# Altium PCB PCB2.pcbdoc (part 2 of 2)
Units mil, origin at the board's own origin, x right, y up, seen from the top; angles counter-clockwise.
Board outline 4275 x 4381.77 mil, 2 copper layers (Top Layer, Bottom Layer); 56 components, 70 nets, 265 pads, 133 vias.
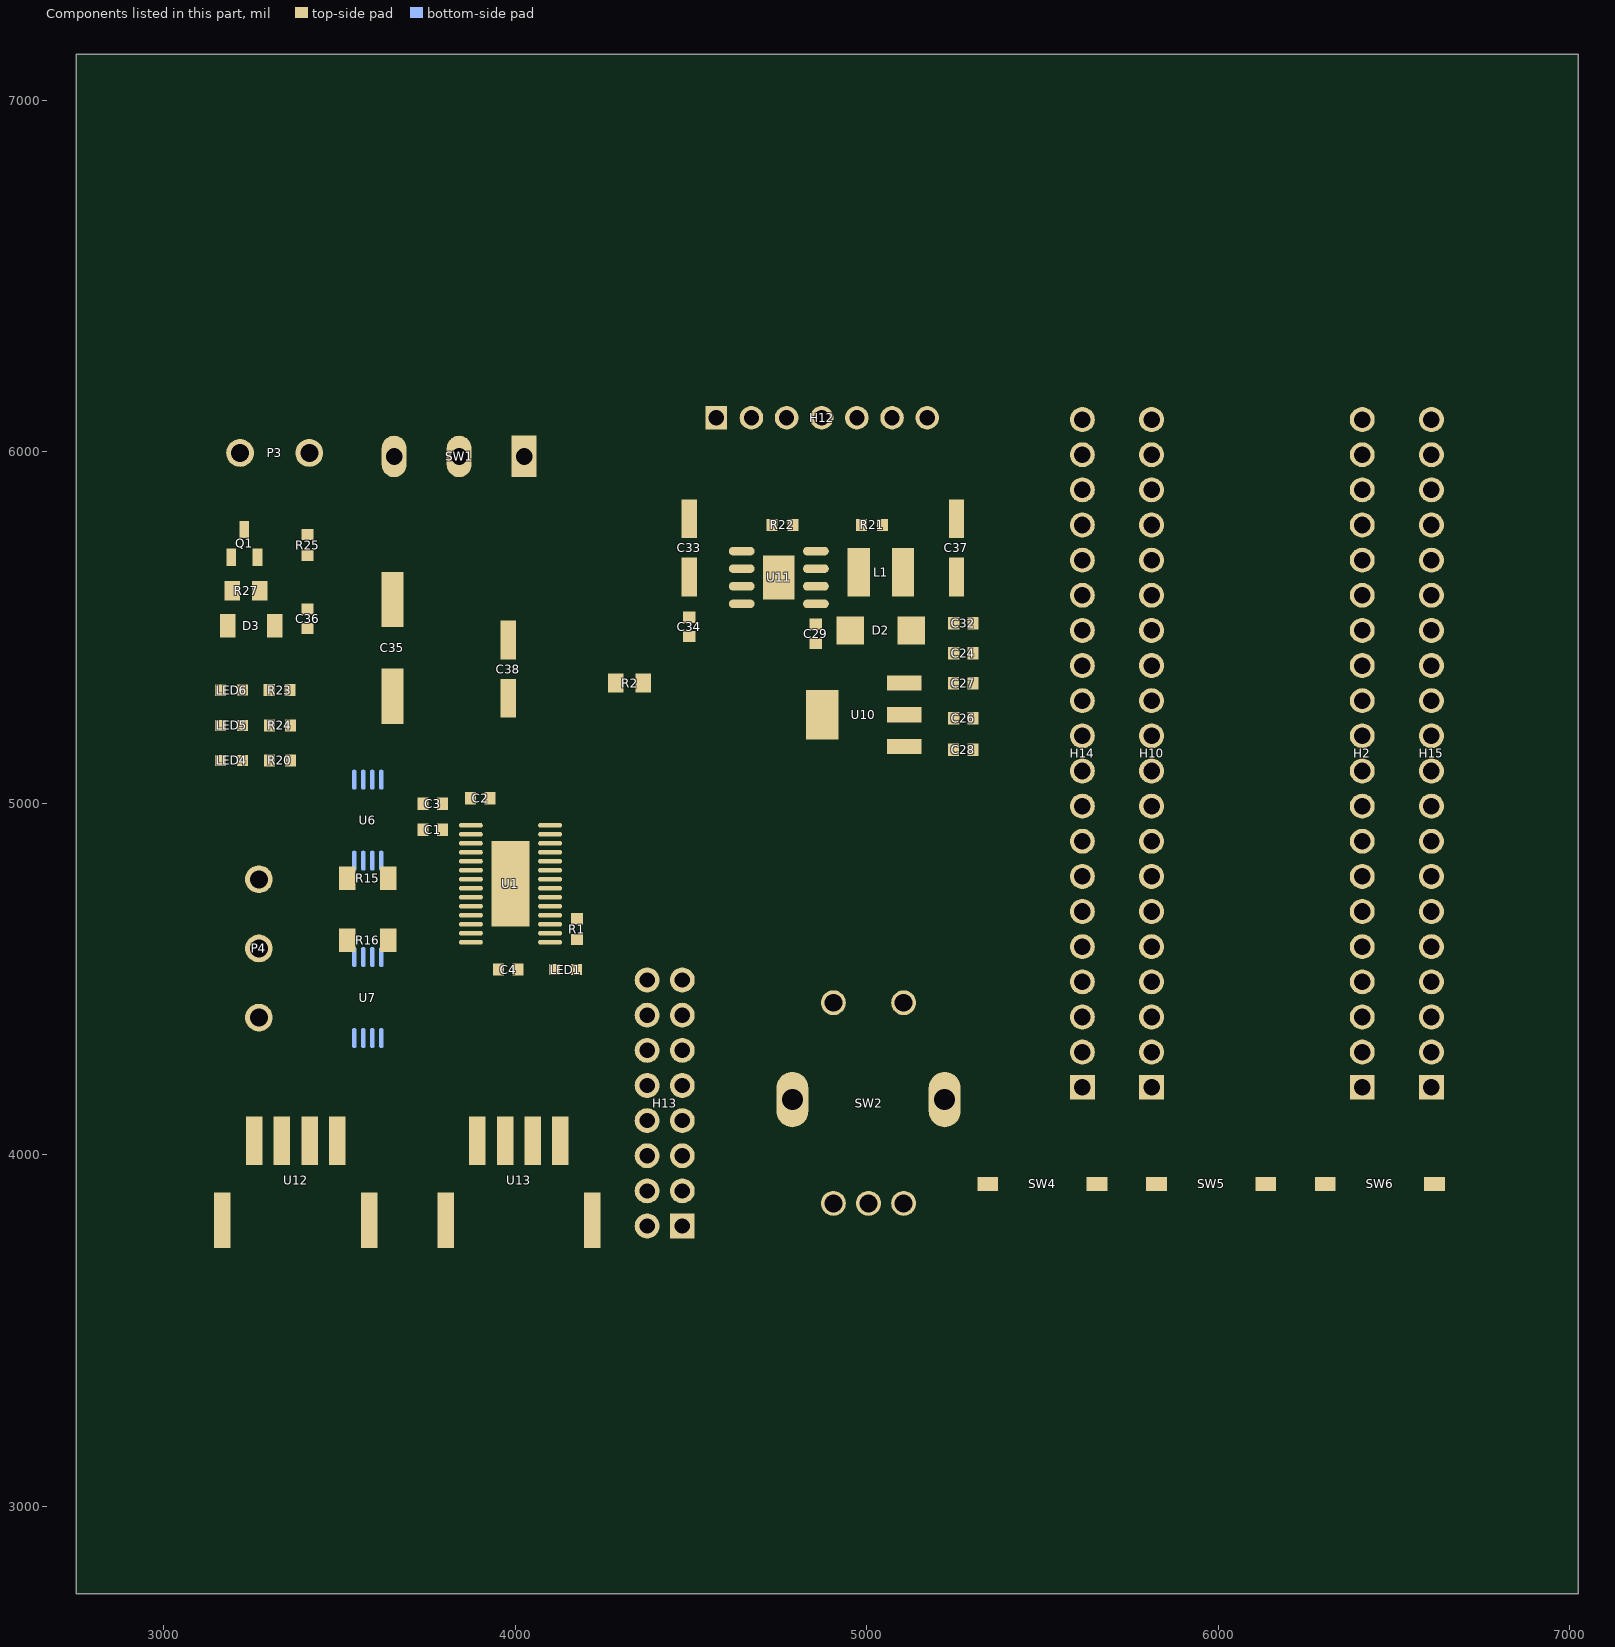
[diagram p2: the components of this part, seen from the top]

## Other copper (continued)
Bottom Layer:
  region net VCC-3.3V: 3525,5101.77 3525,5026.77 3535,5016.77 3565,5016.77 3575,5026.77 3575,5101.77 3570,5106.77 3530,5106.77
  region net PB1: 6458.45,5596.77 6458.45,5586.77 6455.65,5586.65 6453.26,5586.29 6451.22,5585.72 6449.48,5584.93 6447.99,5583.96 6446.69,5582.82 6445.55,5581.52 6444.51,5580.08 6442.51,5576.84 6440.3,5573.22 6438.99,5571.31 6437.48,5569.35 6435.71,5567.36 6433.63,5565.35 6433.63,5618.2 6435.71,5616.19 6437.48,5614.2 6438.99,5612.24 6440.3,5610.33 6442.51,5606.71 6444.51,5603.47 6445.55,5602.03 6446.69,5600.73 6447.99,5599.59 6449.48,5598.62 6451.22,5597.83 6453.26,5597.26 6455.65,5596.9
  region net PB0: 6458.45,5496.77 6458.45,5486.77 6455.65,5486.65 6453.26,5486.29 6451.22,5485.72 6449.48,5484.93 6447.99,5483.96 6446.69,5482.82 6445.55,5481.52 6444.51,5480.08 6442.51,5476.84 6440.3,5473.22 6438.99,5471.31 6437.48,5469.35 6435.71,5467.36 6433.63,5465.35 6433.63,5518.2 6435.71,5516.19 6437.48,5514.2 6438.99,5512.24 6440.3,5510.33 6442.51,5506.71 6444.51,5503.47 6445.55,5502.03 6446.69,5500.73 6447.99,5499.59 6449.48,5498.62 6451.22,5497.83 6453.26,5497.26 6455.65,5496.9
  region net PA7: 6458.45,5396.77 6458.45,5386.77 6455.65,5386.65 6453.26,5386.29 6451.22,5385.72 6449.48,5384.93 6447.99,5383.96 6446.69,5382.82 6445.55,5381.52 6444.51,5380.08 6442.51,5376.84 6440.3,5373.22 6438.99,5371.31 6437.48,5369.35 6435.71,5367.36 6433.63,5365.35 6433.63,5418.2 6435.71,5416.19 6437.48,5414.2 6438.99,5412.24 6440.3,5410.33 6442.51,5406.71 6444.51,5403.47 6445.55,5402.03 6446.69,5400.73 6447.99,5399.59 6449.48,5398.62 6451.22,5397.83 6453.26,5397.26 6455.65,5396.9
  region net PA6: 6458.45,5296.77 6458.45,5286.77 6455.65,5286.65 6453.26,5286.29 6451.22,5285.72 6449.48,5284.93 6447.99,5283.96 6446.69,5282.82 6445.55,5281.52 6444.51,5280.08 6442.51,5276.84 6440.3,5273.22 6438.99,5271.31 6437.48,5269.35 6435.71,5267.36 6433.63,5265.35 6433.63,5318.2 6435.71,5316.19 6437.48,5314.2 6438.99,5312.24 6440.3,5310.33 6442.51,5306.71 6444.51,5303.47 6445.55,5302.03 6446.69,5300.73 6447.99,5299.59 6449.48,5298.62 6451.22,5297.83 6453.26,5297.26 6455.65,5296.9
  region net PA5: 6458.45,5196.77 6458.45,5186.77 6455.65,5186.65 6453.26,5186.29 6451.22,5185.72 6449.48,5184.93 6447.99,5183.96 6446.69,5182.82 6445.55,5181.52 6444.51,5180.08 6442.51,5176.84 6440.3,5173.22 6438.99,5171.31 6437.48,5169.35 6435.71,5167.36 6433.63,5165.35 6433.63,5218.2 6435.71,5216.19 6437.48,5214.2 6438.99,5212.24 6440.3,5210.33 6442.51,5206.71 6444.51,5203.47 6445.55,5202.03 6446.69,5200.73 6447.99,5199.59 6449.48,5198.62 6451.22,5197.83 6453.26,5197.26 6455.65,5196.9
  region net PB12: 5848.19,6061.05 5841.12,6053.98 5839.05,6055.87 5837.11,6057.31 5835.25,6058.34 5833.47,6059.02 5831.73,6059.39 5830.01,6059.5 5828.28,6059.39 5826.52,6059.1 5822.82,6058.22 5818.7,6057.22 5816.42,6056.8 5813.97,6056.49 5811.31,6056.33 5808.42,6056.38 5845.79,6093.75 5845.84,6090.86 5845.68,6088.2 5845.37,6085.75 5844.94,6083.47 5843.94,6079.35 5843.06,6075.64 5842.78,6073.89 5842.67,6072.16 5842.78,6070.44 5843.15,6068.7 5843.82,6066.91 5844.86,6065.06 5846.3,6063.11
  region net PB13: 5849.32,5974.52 5853.14,5956.57 5851.28,5958.23 5849.4,5959.55 5847.48,5960.56 5845.53,5961.29 5843.55,5961.76 5841.52,5961.99 5839.46,5962.02 5837.35,5961.87 5833.01,5961.13 5828.49,5959.99 5818.82,5957.34 5843.68,6003.97 5844.23,6002.17 5844.62,6000.3 5845.02,5996.4 5845.14,5988.38 5845.34,5984.47 5845.57,5982.6 5845.94,5980.79 5846.47,5979.06 5847.19,5977.43 5848.13,5975.92
  region net PA10: 5772.6,5522.5 5779.67,5529.57 5781.73,5527.68 5783.68,5526.24 5785.53,5525.2 5787.32,5524.53 5789.06,5524.16 5790.78,5524.05 5792.51,5524.16 5794.26,5524.44 5797.97,5525.33 5802.09,5526.32 5804.37,5526.75 5806.82,5527.06 5809.48,5527.22 5812.37,5527.17 5775,5489.8 5774.95,5492.69 5775.1,5495.35 5775.42,5497.8 5775.84,5500.08 5776.84,5504.2 5777.72,5507.9 5778.01,5509.66 5778.12,5511.39 5778.01,5513.11 5777.64,5514.85 5776.96,5516.64 5775.93,5518.49 5774.49,5520.43
  region net VCC-3.3V: 4686.85,6051.04 4656.85,6051.04 4656.63,6053.96 4656,6057.06 4655.02,6060.26 4653.74,6063.46 4652.24,6066.58 4650.56,6069.51 4648.76,6072.17 4646.91,6074.46 4696.79,6074.46 4694.94,6072.17 4693.14,6069.51 4691.46,6066.58 4689.96,6063.46 4688.69,6060.26 4687.7,6057.06 4687.07,6053.96
  region net AS5600_SCL: 4335.2,4476.77 4317.62,4486.77 4319.98,4486.91 4322.21,4487.31 4324.3,4487.96 4326.26,4488.83 4328.1,4489.91 4329.83,4491.19 4331.46,4492.64 4332.98,4494.25 4335.75,4497.87 4338.22,4501.92 4340.42,4506.24 4342.42,4510.7 4364.78,4462.85 4362.68,4463.58 4360.69,4464.45 4356.98,4466.49 4353.52,4468.78 4350.18,4471.12 4346.81,4473.29 4343.29,4475.09 4341.42,4475.79 4339.46,4476.32 4337.39,4476.66
  region net AS5600_SDA: 4326.57,4391.77 4326.57,4401.77 4329.37,4401.9 4331.76,4402.26 4333.8,4402.83 4335.54,4403.61 4337.03,4404.58 4338.32,4405.73 4339.47,4407.02 4340.51,4408.46 4342.5,4411.71 4344.71,4415.32 4346.02,4417.23 4347.53,4419.19 4349.3,4421.18 4351.38,4423.18 4351.38,4370.36 4349.3,4372.37 4347.53,4374.36 4346.02,4376.32 4344.71,4378.23 4342.5,4381.84 4340.51,4385.08 4339.47,4386.52 4338.32,4387.82 4337.03,4388.96 4335.54,4389.93 4333.8,4390.72 4331.76,4391.29 4329.37,4391.65
  region net M0_IN3: 4330.54,4286.77 4323.08,4296.77 4325.71,4296.91 4328.04,4297.29 4330.09,4297.9 4331.9,4298.73 4333.51,4299.77 4334.95,4300.98 4336.26,4302.37 4337.48,4303.9 4339.75,4307.36 4342.06,4311.21 4344.68,4315.33 4347.89,4319.59 4355.34,4267.29 4352.54,4269.53 4349.62,4272.39 4343.49,4278.86 4340.32,4281.89 4337.09,4284.42 4335.46,4285.39 4333.82,4286.14 4332.18,4286.61
  region net M0_IN2: 4326.57,4191.77 4326.57,4201.77 4329.37,4201.9 4331.76,4202.26 4333.8,4202.83 4335.54,4203.61 4337.03,4204.58 4338.32,4205.73 4339.47,4207.02 4340.51,4208.46 4342.5,4211.71 4344.71,4215.32 4346.02,4217.23 4347.53,4219.19 4349.3,4221.18 4351.38,4223.18 4351.38,4170.36 4349.3,4172.37 4347.53,4174.36 4346.02,4176.32 4344.71,4178.23 4342.5,4181.84 4340.51,4185.08 4339.47,4186.52 4338.32,4187.82 4337.03,4188.96 4335.54,4189.93 4333.8,4190.72 4331.76,4191.29 4329.37,4191.65
  region net M0_OUT2_CS: 4326.57,3891.77 4326.57,3901.77 4329.37,3901.9 4331.76,3902.26 4333.8,3902.83 4335.54,3903.61 4337.03,3904.58 4338.32,3905.73 4339.47,3907.02 4340.51,3908.46 4342.5,3911.71 4344.71,3915.32 4346.02,3917.23 4347.53,3919.19 4349.3,3921.18 4351.38,3923.18 4351.38,3870.36 4349.3,3872.37 4347.53,3874.36 4346.02,3876.32 4344.71,3878.23 4342.5,3881.84 4340.51,3885.08 4339.47,3886.52 4338.32,3887.82 4337.03,3888.96 4335.54,3889.93 4333.8,3890.72 4331.76,3891.29 4329.37,3891.65
  region net M0_OUT1_CS: 4326.57,3791.77 4326.57,3801.77 4329.37,3801.9 4331.76,3802.26 4333.8,3802.83 4335.54,3803.61 4337.03,3804.58 4338.32,3805.73 4339.47,3807.02 4340.51,3808.46 4342.5,3811.71 4344.71,3815.32 4346.02,3817.23 4347.53,3819.19 4349.3,3821.18 4351.38,3823.18 4351.38,3770.36 4349.3,3772.37 4347.53,3774.36 4346.02,3776.32 4344.71,3778.23 4342.5,3781.84 4340.51,3785.08 4339.47,3786.52 4338.32,3787.82 4337.03,3788.96 4335.54,3789.93 4333.8,3790.72 4331.76,3791.29 4329.37,3791.65
  region net PB12: 5578.54,6054.7 5575.2,6065.5 5576.21,6066.76 5577.02,6068.25 5577.63,6069.95 5578.08,6071.82 5578.55,6075.98 5578.63,6080.48 5578.29,6089.59 5578.25,6093.73 5578.52,6097.27 5611.98,6056.36 5609.21,6056.57 5606.61,6056.92 5601.85,6057.9 5597.55,6058.97 5593.59,6059.82 5591.7,6060.06 5589.84,6060.14 5588,6059.99 5586.17,6059.6 5584.32,6058.91 5582.45,6057.89 5580.52,6056.5
  region net PB13: 5578.54,5954.7 5575.2,5965.5 5576.21,5966.76 5577.02,5968.25 5577.63,5969.95 5578.08,5971.82 5578.55,5975.98 5578.63,5980.48 5578.29,5989.59 5578.25,5993.73 5578.52,5997.27 5611.98,5956.36 5609.21,5956.57 5606.61,5956.92 5601.85,5957.9 5597.55,5958.97 5593.59,5959.82 5591.7,5960.06 5589.84,5960.14 5588,5959.99 5586.17,5959.6 5584.32,5958.91 5582.45,5957.89 5580.52,5956.5
  region net PB14: 5574.02,5855.69 5574.78,5870.6 5575.89,5871.92 5576.76,5873.42 5577.43,5875.08 5577.92,5876.87 5578.46,5880.78 5578.61,5884.97 5578.53,5893.51 5578.72,5897.52 5578.97,5899.38 5579.35,5901.12 5608.05,5856.75 5602.92,5857.77 5598.16,5858.96 5593.71,5860.09 5589.52,5860.88 5587.49,5861.08 5585.51,5861.1 5583.56,5860.91 5581.64,5860.47 5579.73,5859.77 5577.83,5858.76 5575.93,5857.41
  region net PA8: 5561.6,5691.77 5569.06,5701.77 5570.7,5701.94 5572.35,5702.41 5573.98,5703.16 5575.61,5704.13 5578.84,5706.66 5582.02,5709.69 5588.15,5716.16 5591.07,5719.03 5593.87,5721.27 5586.42,5668.95 5583.21,5673.21 5580.59,5677.33 5578.28,5681.19 5576,5684.64 5574.79,5686.18 5573.48,5687.56 5572.03,5688.78 5570.42,5689.81 5568.61,5690.65 5566.56,5691.26 5564.24,5691.64
  region net PB4: 5565.1,4986.77 5565.1,4996.77 5567.89,4996.9 5570.28,4997.26 5572.33,4997.83 5574.07,4998.62 5575.56,4999.59 5576.85,5000.73 5577.99,5002.03 5579.04,5003.47 5581.03,5006.71 5583.24,5010.33 5584.55,5012.24 5586.06,5014.2 5587.83,5016.19 5589.91,5018.2 5589.91,4965.35 5587.83,4967.36 5586.06,4969.35 5584.55,4971.31 5583.24,4973.22 5581.03,4976.84 5579.04,4980.08 5577.99,4981.52 5576.85,4982.82 5575.56,4983.96 5574.07,4984.93 5572.33,4985.72 5570.28,4986.29 5567.89,4986.65
  region net PB1: 6558.4,5586.77 6558.4,5596.77 6561.2,5596.9 6563.59,5597.26 6565.63,5597.83 6567.37,5598.62 6568.86,5599.59 6570.16,5600.73 6571.3,5602.03 6572.34,5603.47 6574.34,5606.71 6576.55,5610.33 6577.86,5612.24 6579.37,5614.2 6581.14,5616.19 6583.22,5618.2 6583.22,5565.35 6581.14,5567.36 6579.37,5569.35 6577.86,5571.31 6576.55,5573.22 6574.34,5576.84 6572.34,5580.08 6571.3,5581.52 6570.16,5582.82 6568.86,5583.96 6567.37,5584.93 6565.63,5585.72 6563.59,5586.29 6561.2,5586.65
  region net PB0: 6558.4,5486.77 6558.4,5496.77 6561.2,5496.9 6563.59,5497.26 6565.63,5497.83 6567.37,5498.62 6568.86,5499.59 6570.16,5500.73 6571.3,5502.03 6572.34,5503.47 6574.34,5506.71 6576.55,5510.33 6577.86,5512.24 6579.37,5514.2 6581.14,5516.19 6583.22,5518.2 6583.22,5465.35 6581.14,5467.36 6579.37,5469.35 6577.86,5471.31 6576.55,5473.22 6574.34,5476.84 6572.34,5480.08 6571.3,5481.52 6570.16,5482.82 6568.86,5483.96 6567.37,5484.93 6565.63,5485.72 6563.59,5486.29 6561.2,5486.65
  region net PA7: 6558.4,5386.77 6558.4,5396.77 6561.2,5396.9 6563.59,5397.26 6565.63,5397.83 6567.37,5398.62 6568.86,5399.59 6570.16,5400.73 6571.3,5402.03 6572.34,5403.47 6574.34,5406.71 6576.55,5410.33 6577.86,5412.24 6579.37,5414.2 6581.14,5416.19 6583.22,5418.2 6583.22,5365.35 6581.14,5367.36 6579.37,5369.35 6577.86,5371.31 6576.55,5373.22 6574.34,5376.84 6572.34,5380.08 6571.3,5381.52 6570.16,5382.82 6568.86,5383.96 6567.37,5384.93 6565.63,5385.72 6563.59,5386.29 6561.2,5386.65
  region net PA6: 6558.4,5286.77 6558.4,5296.77 6561.2,5296.9 6563.59,5297.26 6565.63,5297.83 6567.37,5298.62 6568.86,5299.59 6570.16,5300.73 6571.3,5302.03 6572.34,5303.47 6574.34,5306.71 6576.55,5310.33 6577.86,5312.24 6579.37,5314.2 6581.14,5316.19 6583.22,5318.2 6583.22,5265.35 6581.14,5267.36 6579.37,5269.35 6577.86,5271.31 6576.55,5273.22 6574.34,5276.84 6572.34,5280.08 6571.3,5281.52 6570.16,5282.82 6568.86,5283.96 6567.37,5284.93 6565.63,5285.72 6563.59,5286.29 6561.2,5286.65
  region net PA5: 6558.4,5186.77 6558.4,5196.77 6561.2,5196.9 6563.59,5197.26 6565.63,5197.83 6567.37,5198.62 6568.86,5199.59 6570.16,5200.73 6571.3,5202.03 6572.34,5203.47 6574.34,5206.71 6576.55,5210.33 6577.86,5212.24 6579.37,5214.2 6581.14,5216.19 6583.22,5218.2 6583.22,5165.35 6581.14,5167.36 6579.37,5169.35 6577.86,5171.31 6576.55,5173.22 6574.34,5176.84 6572.34,5180.08 6571.3,5181.52 6570.16,5182.82 6568.86,5183.96 6567.37,5184.93 6565.63,5185.72 6563.59,5186.29 6561.2,5186.65
  region net M0_OUT1_P: 3597.79,4799.86 3587.79,4799.86 3587.71,4802.62 3587.49,4805.23 3586.82,4809.8 3585.84,4814.86 3599.74,4814.86 3598.76,4809.8 3598.09,4805.23 3597.87,4802.62
  region net M0_OUT1_N: 3572.2,4799.86 3562.2,4799.86 3562.12,4802.62 3561.9,4805.23 3561.23,4809.8 3560.25,4814.86 3574.15,4814.86 3573.17,4809.8 3572.5,4805.23 3572.28,4802.62
  region net GND: 3536.61,4873.21 3546.61,4873.21 3546.69,4870.45 3546.91,4867.84 3547.58,4863.27 3548.56,4858.21 3534.66,4858.21 3535.64,4863.27 3536.31,4867.84 3536.53,4870.45
  region net M0_OUT1_CS: 3615,5105.3 3625,5102.08 3625.15,5098.62 3625.41,5094.54 3625.51,5090.48 3625.4,5088.65 3625.15,5087.08 3611.63,5090.3 3612.87,5094.6 3613.95,5097.72 3614.38,5099.22 3614.71,5100.88 3614.92,5102.85
  region net GND: 3586.81,5102.71 3596.81,5104.67 3596.9,5102.77 3597.16,5100.89 3597.97,5097.15 3598.92,5093.42 3599.67,5089.67 3585.91,5087.71 3585.73,5089.65 3585.73,5091.53 3586.08,5095.19 3586.56,5098.86
  region net VCC-3.3V: 3575.43,5022.84 3560.43,5022.84 3560.25,5045.34 3574.15,5045.34 3574.79,5037.94 3575.23,5030.96
  region net M0_OUT2_N: 3552.53,4597.17 3566.55,4597.29 3569.35,4594.32 3570.63,4592.74 3571.78,4591.08 3572.76,4589.35 3573.51,4587.55 3573.99,4585.66 3574.16,4583.69 3560.26,4583.69 3560.09,4585.68 3559.6,4587.56 3558.83,4589.34 3557.85,4591.03 3556.68,4592.65 3555.37,4594.2
  region net M0_OUT2_P: 3593.45,4597.3 3607.47,4597.18 3604.64,4594.21 3603.33,4592.65 3602.16,4591.03 3601.17,4589.34 3600.41,4587.56 3599.92,4585.68 3599.75,4583.69 3585.85,4583.69 3586.02,4585.66 3586.5,4587.55 3587.25,4589.35 3588.23,4591.08 3589.38,4592.74 3590.66,4594.32
  region net GND: 3625,4526.95 3615,4523.73 3614.92,4526.17 3614.71,4528.15 3614.38,4529.81 3613.95,4531.31 3612.87,4534.43 3611.63,4538.73 3625.15,4541.95 3625.4,4540.38 3625.51,4538.55 3625.41,4534.49 3625.15,4530.41
  region net M0_OUT2_CS: 3545,4293.25 3535,4296.47 3534.85,4299.93 3534.59,4304.01 3534.49,4308.07 3534.6,4309.9 3534.85,4311.47 3548.37,4308.25 3547.13,4303.95 3546.05,4300.83 3545.62,4299.33 3545.29,4297.67 3545.08,4295.69
  region net GND: 3562.21,4368.21 3572.21,4368.21 3572.29,4365.45 3572.51,4362.84 3573.18,4358.27 3574.16,4353.21 3560.26,4353.21 3561.24,4358.27 3561.91,4362.84 3562.13,4365.45
  region net VCC-3.3V: 3600,4294.86 3590,4294.86 3589.82,4297.62 3589.35,4300.23 3588.69,4302.64 3587.93,4304.8 3586.5,4308.15 3585.85,4309.86 3599.75,4309.86 3599.87,4304.8
  region net VCC-3.3V: 3623.39,4294.86 3613.39,4294.86 3613.31,4297.62 3613.09,4300.23 3612.42,4304.8 3611.44,4309.86 3625.34,4309.86 3624.36,4304.8 3623.69,4300.23 3623.47,4297.62
  region net PB13: 4942.77,4401.5 4935.7,4394.43 4933.64,4396.32 4931.69,4397.76 4929.84,4398.79 4928.06,4399.47 4926.32,4399.84 4924.6,4399.95 4922.87,4399.83 4921.12,4399.55 4917.41,4398.67 4913.3,4397.68 4911.02,4397.25 4908.56,4396.94 4905.91,4396.78 4903.02,4396.83 4940.37,4434.18 4940.42,4431.3 4940.27,4428.64 4939.95,4426.18 4939.53,4423.91 4938.53,4419.79 4937.65,4416.09 4937.37,4414.33 4937.26,4412.6 4937.36,4410.88 4937.73,4409.14 4938.41,4407.36 4939.45,4405.51 4940.88,4403.56
  region net PA8: 5378.07,5611.91 5385.14,5604.84 5384.41,5603.99 5383.79,5603.01 5382.84,5600.8 5382.26,5598.42 5381.99,5596.11 5369.33,5608.76 5371.65,5609.03 5374.02,5609.61 5376.24,5610.56 5377.21,5611.18
  region net PB14: 5473.07,5768.88 5480.14,5761.81 5479.41,5760.96 5478.79,5759.98 5477.84,5757.77 5477.26,5755.39 5476.99,5753.07 5464.33,5765.73 5466.65,5766 5469.02,5766.58 5471.24,5767.53 5472.21,5768.15
  region net PB13: 5467.41,5813.74 5478.61,5810.79 5477.79,5809.86 5477.07,5808.79 5476.46,5807.62 5476,5806.39 5475.71,5805.12 5475.6,5803.85 5475.71,5802.62 5476.06,5801.46 5459.12,5807.24 5461.21,5808.57 5463.45,5810.25
  region net PB4: 5461.41,4996.77 5461.41,4986.77 5460.29,4986.69 5459.16,4986.43 5456.93,4985.54 5454.83,4984.27 5453.01,4982.82 5453.01,5000.72 5454.83,4999.27 5456.93,4998.01 5459.16,4997.11 5460.29,4996.86
  region net M0_IN2: 4306.41,4201.77 4306.41,4191.77 4305.29,4191.69 4304.16,4191.43 4301.93,4190.54 4299.83,4189.27 4298.01,4187.82 4298.01,4205.72 4299.83,4204.27 4301.93,4203.01 4304.16,4202.11 4305.29,4201.86
  region net M0_IN3: 4271.41,4296.77 4271.41,4286.77 4270.29,4286.69 4269.16,4286.43 4266.93,4285.54 4264.83,4284.27 4263.01,4282.82 4263.01,4300.72 4264.83,4299.27 4266.93,4298.01 4269.16,4297.11 4270.29,4296.86
  region net AS5600_SDA: 4211.41,4401.77 4211.41,4391.77 4210.29,4391.69 4209.16,4391.43 4206.93,4390.54 4204.83,4389.27 4203.01,4387.82 4203.01,4405.72 4204.83,4404.27 4206.93,4403.01 4209.16,4402.11 4210.29,4401.86
  region net AS5600_SCL: 4211.41,4486.77 4211.41,4476.77 4210.29,4476.69 4209.16,4476.43 4206.93,4475.54 4204.83,4474.27 4203.01,4472.82 4203.01,4490.72 4204.83,4489.27 4206.93,4488.01 4209.16,4487.11 4210.29,4486.86
  region net PA9: 3965.63,4056.38 3975.63,4056.38 3975.72,4055.26 3975.97,4054.13 3976.87,4051.89 3978.13,4049.8 3979.58,4047.97 3961.68,4047.97 3963.13,4049.8 3964.4,4051.89 3965.29,4054.13 3965.54,4055.26
  region net PA10: 3886.89,4056.37 3896.89,4056.37 3896.98,4055.25 3897.23,4054.12 3898.13,4051.88 3899.39,4049.79 3900.84,4047.96 3882.94,4047.96 3884.39,4049.79 3885.66,4051.88 3886.55,4054.12 3886.8,4055.25
  region net M0_OUT2_N: 3538.19,4615.15 3538.19,4605.15 3537.07,4605.06 3535.94,4604.81 3533.71,4603.92 3531.61,4602.65 3529.79,4601.2 3529.79,4619.1 3531.61,4617.65 3533.71,4616.39 3535.94,4615.49 3537.07,4615.24
  region net M0_OUT2_P: 3621.81,4605.15 3621.81,4615.15 3622.93,4615.24 3624.06,4615.49 3626.29,4616.39 3628.39,4617.65 3630.21,4619.1 3630.21,4601.2 3628.39,4602.65 3626.29,4603.92 3624.06,4604.81 3622.93,4605.06
  region net M0_OUT1_N: 3538.19,4791.77 3538.19,4781.77 3537.07,4781.69 3535.94,4781.43 3533.71,4780.54 3531.61,4779.27 3529.79,4777.82 3529.79,4795.72 3531.61,4794.27 3533.71,4793.01 3535.94,4792.11 3537.07,4791.86
  region net M0_OUT1_P: 3621.81,4781.77 3621.81,4791.77 3622.93,4791.86 3624.06,4792.11 3626.29,4793.01 3628.39,4794.27 3630.21,4795.72 3630.21,4777.82 3628.39,4779.27 3626.29,4780.54 3624.06,4781.43 3622.93,4781.69
  region net PB13: 5816.43,3901.63 5809.36,3908.71 5810.09,3909.56 5810.71,3910.54 5811.66,3912.75 5812.24,3915.12 5812.51,3917.44 5825.17,3904.78 5822.85,3904.52 5820.48,3903.93 5818.26,3902.99 5817.29,3902.36
  region net PB13: 5832.57,3931.91 5839.64,3924.84 5838.91,3923.99 5838.29,3923.01 5837.34,3920.8 5836.76,3918.42 5836.49,3916.11 5823.83,3928.76 5826.15,3929.03 5828.52,3929.61 5830.74,3930.56 5831.71,3931.18
  region net PB12: 6299.5,3933.18 6309.5,3933.18 6309.59,3932.06 6309.84,3930.93 6310.73,3928.7 6312,3926.61 6313.45,3924.78 6295.55,3924.78 6297,3926.61 6298.27,3928.7 6299.16,3930.93 6299.41,3932.06
  region net PB14: 5359.64,3908.71 5352.57,3901.63 5351.71,3902.36 5350.74,3902.99 5348.52,3903.93 5346.15,3904.52 5343.83,3904.78 5356.49,3917.44 5356.76,3915.12 5357.34,3912.75 5358.29,3910.54 5358.91,3909.56
  region net PB14: 5965.14,5863.71 5958.07,5856.63 5957.21,5857.36 5956.24,5857.99 5954.02,5858.93 5951.65,5859.52 5949.33,5859.78 5961.99,5872.44 5962.26,5870.12 5962.84,5867.75 5963.79,5865.54 5964.41,5864.56
  region net VCC-3.3V: 5241.14,5224.87 5230.53,5235.47 5232.29,5237.1 5233.82,5238.59 5234.44,5239.38 5234.94,5240.26 5235.28,5241.27 5235.45,5242.44 5248.11,5229.78 5246.93,5229.62 5245.93,5229.27 5245.05,5228.78 5244.25,5228.15 5242.76,5226.62
  region net VCC-3.3V: 3590,4293.19 3600,4293.19 3600.09,4292.06 3600.34,4290.93 3601.23,4288.7 3602.5,4286.61 3603.95,4284.78 3586.05,4284.78 3587.5,4286.61 3588.77,4288.7 3589.66,4290.93 3589.91,4292.06
  region net VCC-3.3V: 3613.39,4286.57 3623.39,4297.04 3623.36,4293.72 3623.43,4292.21 3623.64,4290.88 3624.06,4289.79 3624.76,4289.01 3625.79,4288.61 3627.24,4288.63 3617.99,4272.28 3616.3,4276.05 3614.83,4279.26 3614.24,4280.85 3613.79,4282.55 3613.49,4284.43
  region net VCC-5V: 3376.07,5226.77 3376.07,5216.77 3374.95,5216.69 3373.82,5216.43 3371.59,5215.54 3369.49,5214.27 3367.67,5212.82 3367.67,5230.72 3369.49,5229.27 3371.59,5228.01 3373.82,5227.11 3374.95,5226.86
  region net VCC-5V: 5084.86,5349.84 5091.93,5356.91 5092.79,5356.18 5093.76,5355.56 5095.98,5354.61 5098.35,5354.03 5100.67,5353.76 5088.01,5341.11 5087.74,5343.42 5087.16,5345.8 5086.21,5348.01 5085.59,5348.99
  region net GND: 3165.84,5205.16 3155.84,5205.16 3155.75,5206.28 3155.5,5207.42 3154.6,5209.65 3153.34,5211.74 3151.89,5213.57 3169.79,5213.57 3168.34,5211.74 3167.07,5209.65 3166.18,5207.42 3165.93,5206.28
  region net GND: 4698.59,3741.77 4698.59,3751.77 4699.71,3751.86 4700.84,3752.11 4703.07,3753.01 4705.17,3754.27 4706.99,3755.72 4706.99,3737.82 4705.17,3739.27 4703.07,3740.54 4700.84,3741.43 4699.71,3741.69
  region net GND: 4543.59,4906.77 4543.59,4916.77 4544.71,4916.86 4545.84,4917.11 4548.07,4918.01 4550.17,4919.27 4551.99,4920.72 4551.99,4902.82 4550.17,4904.27 4548.07,4905.54 4545.84,4906.43 4544.71,4906.69
  region net GND: 4540.23,4916.77 4540.23,4906.77 4539.11,4906.69 4537.98,4906.43 4535.75,4905.54 4533.65,4904.27 4531.83,4902.82 4531.83,4920.72 4533.65,4919.27 4535.75,4918.01 4537.98,4917.11 4539.11,4916.86
  region net GND: 4507.41,4906.77 4507.41,4916.77 4508.53,4916.86 4509.66,4917.11 4511.9,4918.01 4513.99,4919.27 4515.82,4920.72 4515.82,4902.82 4513.99,4904.27 4511.9,4905.54 4509.66,4906.43 4508.53,4906.69
  region net GND: 4650.85,3741.77 4650.85,3751.77 4651.98,3751.86 4653.11,3752.11 4655.34,3753.01 4657.43,3754.27 4659.26,3755.72 4659.26,3737.82 4657.43,3739.27 4655.34,3740.54 4653.11,3741.43 4651.98,3741.69
  region net GND: 4683.68,3751.77 4683.68,3741.77 4682.56,3741.69 4681.42,3741.43 4679.19,3740.54 4677.1,3739.27 4675.27,3737.82 4675.27,3755.72 4677.1,3754.27 4679.19,3753.01 4681.42,3752.11 4682.56,3751.86
  region net GND: 3429.76,4034.08 3424.51,4025.2 3423.65,4025.91 3422.63,4026.53 3420.28,4027.46 3417.78,4027.96 3415.43,4028.01 3426.14,4042.35 3426.66,4040.12 3427.39,4037.91 3428.4,4035.85
  region net GND: 3399.6,4050.1 3408.49,4055.36 3410.25,4053.99 3412.31,4052.98 3414.53,4052.26 3416.75,4051.74 3402.41,4041.02 3402.37,4043.37 3401.87,4045.88 3400.94,4048.23 3400.32,4049.24
  region net GND: 3165.84,5105.11 3155.84,5105.11 3155.75,5106.23 3155.5,5107.36 3154.6,5109.6 3153.34,5111.69 3151.89,5113.52 3169.79,5113.52 3168.34,5111.69 3167.07,5109.6 3166.18,5107.36 3165.93,5106.23
  region net GND: 3155.84,5137.93 3165.84,5137.93 3165.93,5136.81 3166.18,5135.68 3167.07,5133.45 3168.34,5131.35 3169.79,5129.53 3151.89,5129.53 3153.34,5131.35 3154.6,5133.45 3155.5,5135.68 3155.75,5136.81
  region net VCC-3.3V: 3719.38,4287.38 ccw(c3656.55,4350.2) 3745,4341.77 3760,4306.79 3745,4240.58 ccw(c3668.51,4240.58) 3740.59,4266.17
  region net GND: 3615,4483.85 cw(c3514.29,4483.85) 3607.93,4446.77 3620,4451.77 3632.07,4470.92 cw(c3665.71,4493.85) 3625,4493.85
  region net GND: 3705,4573.85 cw(c3604.29,4573.85) 3697.93,4536.77 3710,4541.77 3722.07,4560.92 cw(c3755.71,4583.85) 3715,4583.85
  region net GND: 3511.21,4925.32 cw(c3582.43,4996.53) 3490,4956.53 3485,4944.46 3490,4922.39 cw(c3482.43,4882.39) 3511.21,4911.18

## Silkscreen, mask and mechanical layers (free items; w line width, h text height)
Top Silkscreen Layer:
  lines w10: 4503.23,3741.77 4742.9,3741.77 4742.9,4552.27 4516.4,4552.27 ; 4525,3846.77 4745,3846.77 ; 4525,3948.21 4525.88,3949.09 4742.9,3949.09 ; 4525,4044.78 4745,4044.78 ; 4525,4149.52 4742.9,4149.52 ; 4525,4244.95 4741.83,4244.95 4745,4241.77 ; 4525,4351.18 4742.9,4351.18 ; 4525,4453.01 4743.76,4453.01 4745,4451.77 ; 4635.8,3741.77 4635.8,4552.27 ; 4325,4602.68 5418.7,4602.68 5418.7,6146.77 4325,6146.77 4325,4602.68 ; 5701.14,4070.51 6519.25,4070.51 6519.25,6147.68 5701.14,6147.68 5701.14,4070.51 ; 5972.4,5957.27 6247.99,5957.27 6247.99,6147.68 5972.4,6147.68 5972.4,5957.27
  text "+" at 3455,5761.77 h70.87
  text "-" at 3133.33,5761.34 h70.87
  text "ON" at 3580,5741.77 h70.87
  text "OFF" at 3975,5731.77 h70.87
  text "VIN" at 3399.45,5299.27 h45
  text "+5V" at 3399.45,5199.27 h45
  text "3V3" at 3402.26,5099.27 h45
  text "OUT1" at 3432.5,4806.72 h45 r270
  text "OUT2" at 3432.5,4637.37 h45 r270
  text "PA8" at 4648.35,4478.02 h45
  text "SCL" at 4543.8,4474.27 h45
  text "STATE" at 4080,4441.77 h45
  text "OUT3" at 3432.5,4437.37 h45 r270
  text "JLCJLCJLCJLC" at 3385,4406.77 h45 r90
  text "PB4" at 4648.35,4376.95 h45
  text "SDA" at 4543.8,4373.2 h45
  text "PB0" at 4648.35,4275.88 h45
  text "IN3" at 4543.8,4272.13 h45
  text "PA7" at 4648.35,4174.81 h45
  text "IN2" at 4543.8,4171.06 h45
  text "SDA" at 3277.5,4131.22 h45 r90
  text "SCL" at 3357.5,4131.22 h45 r90
  text "GND" at 3437.5,4131.22 h45 r90
  text "3V3" at 3515.61,4130.61 h45 r90
  text "A10" at 3913.44,4130.38 h45 r90
  text "PA9" at 3993.44,4130.38 h45 r90
  text "GND" at 4073.44,4130.38 h45 r90
  text "3V3" at 4151.56,4129.77 h45 r90
  text "PA6" at 4648.35,4073.74 h45
  text "IN1" at 4543.8,4069.99 h45
  text "PB2" at 4648.35,3972.67 h45
  text "EN" at 4543.8,3968.92 h45
  text "PA2" at 4648.35,3871.6 h45
  text "OT2" at 4543.8,3867.85 h45
  text "PB14" at 5450,3789.27 h45
  text "PB13" at 5935.6,3789.27 h45
  text "PB12" at 6420,3789.27 h45
  text "PA1" at 4648.35,3770.52 h45
  text "OT1" at 4543.8,3766.77 h45
Bottom Silkscreen Layer:
  text "-" at 3240,5846.77 h70.87
  text "+" at 3435,5846.77 h70.87
  text "ON" at 3665,5741.77 h70.87
  text "OFF" at 4097.12,5731.34 h70.87
  text "FOC验证板V1.1" at 5255,4811.77 h120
